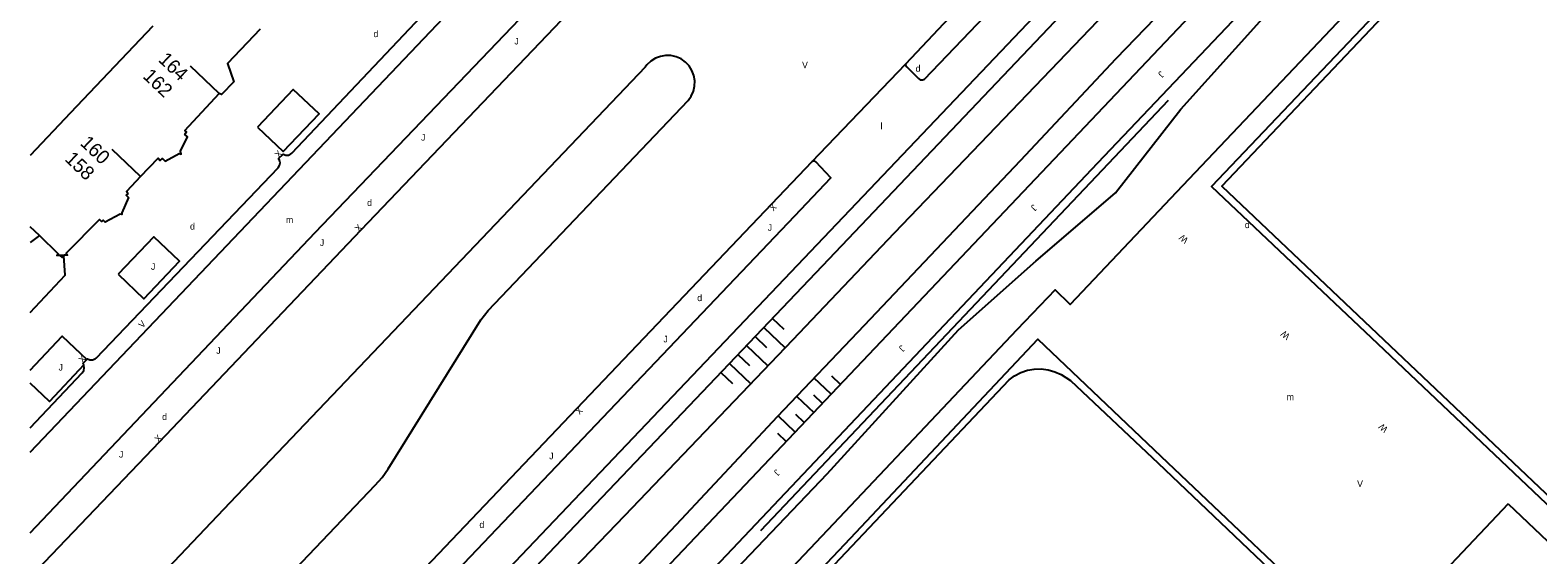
# Model space of a CAD drawing. Extents: x 134999 to 136502, y 457398 to 459002.
# Drawn here: x 135000 to 135114.8, y 457722.8 to 457762.7 of the extents above; entities that cross this region are included whole.
import ezdxf

# ---------------------------------------------------------------- set-up
doc = ezdxf.new("R2010")
doc.units = 0
for name, color, linetype in [('RI_DGTB_15', 7, 'Continuous'), ('RI_DGTB_18', 7, 'Continuous'), ('RI_DGTB_19', 7, 'Continuous'), ('RI_DGTB_2', 7, 'Continuous'), ('RI_DGTB_29', 7, 'Continuous'), ('RI_DGTB_30', 7, 'Continuous'), ('RI_DGTB_31', 7, 'Continuous'), ('RI_DGTB_36', 7, 'Continuous'), ('RI_DGTB_4', 7, 'Continuous'), ('RI_DGTB_43', 7, 'Continuous'), ('RI_DGTB_45', 7, 'Continuous'), ('RI_DGTB_49', 7, 'Continuous'), ('RI_DGTB_5', 7, 'Continuous'), ('RI_DGTB_53', 7, 'Continuous'), ('RI_DGTB_54', 7, 'Continuous'), ('RI_DGTB_55', 7, 'Continuous'), ('RI_DGTB_58', 7, 'Continuous')]:
    doc.layers.add(name, color=color, linetype=linetype)

msp = doc.modelspace()

# ---------------------------------------------------------------- linework, layer by layer
at = {"layer": 'RI_DGTB_15'}
for p, q in [((135014.386, 457757.901), (135012.215, 457759.972)), ((135008.403, 457751.575), (135006.232, 457753.646)), ((135000.718, 457747.078), (135000, 457747.755))]:
    msp.add_line(p, q, dxfattribs=at)
at = {"layer": 'RI_DGTB_18'}
for p, q in [((135044.349, 457717.485), (135122.645, 457800)), ((135056.5, 457740.769), (135057.368, 457739.949)), ((135055.193, 457739.397), (135056.063, 457738.571)), ((135055.847, 457740.083), (135057.474, 457738.542)), ((135054.538, 457738.71), (135056.163, 457737.172)), ((135053.231, 457737.337), (135054.852, 457735.801)), ((135053.885, 457738.023), (135054.759, 457737.195)), ((135052.576, 457736.65), (135053.455, 457735.818)), ((135060.948, 457735.033), (135059.68, 457736.235)), ((135061.687, 457735.757), (135061.034, 457736.375)), ((135058.355, 457734.843), (135059.664, 457733.602)), ((135060.31, 457734.306), (135059.659, 457734.923)), ((135058.245, 457732.13), (135056.945, 457733.362)), ((135058.933, 457732.855), (135058.284, 457733.47)), ((135057.557, 457731.405), (135056.909, 457732.018))]:
    msp.add_line(p, q, dxfattribs=at)
at = {"layer": 'RI_DGTB_19'}
msp.add_line((135076.556, 457745.125), (135082.632, 457750.328), dxfattribs=at)
for points in [[(135046.288, 457715.64), (135081.29, 457752.622), (135113.523, 457786.568), (135126.327, 457800)], [(135082.632, 457750.328), (135087.595, 457756.704), (135097.772, 457768.023), (135114.599, 457785.491), (135126.557, 457798.517), (135128.141, 457800)], [(135076.556, 457745.125), (135070.648, 457739.882), (135060.655, 457728.93)]]:
    msp.add_lwpolyline(points, dxfattribs=at)
at = {"layer": 'RI_DGTB_2'}
for points in [[(135112.51, 457726.659), (135104.213, 457717.881), (135104.437, 457717.669)], [(135112.51, 457726.659), (135121.97, 457717.682)]]:
    msp.add_lwpolyline(points, dxfattribs=at)
at = {"layer": 'RI_DGTB_31'}
for points in [[(135017.307, 457755.344), (135019.264, 457753.484), (135021.989, 457756.35), (135020.032, 457758.21), (135017.307, 457755.344)], [(135006.699, 457744.136), (135008.66, 457742.28), (135011.37, 457745.143), (135009.409, 457746.999), (135006.699, 457744.136)], [(135000, 457736.834), (135002.428, 457739.428), (135004.319, 457737.658)], [(135004.074, 457737.236), (135001.478, 457734.462), (135000, 457735.845)]]:
    msp.add_lwpolyline(points, dxfattribs=at)
at = {"layer": 'RI_DGTB_4'}
for p, q in [((135000.718, 457747.078), (135000, 457746.55)), ((135002.599, 457745.584), (135002.259, 457745.573)), ((135002.599, 457745.584), (135002.561, 457745.545))]:
    msp.add_line(p, q, dxfattribs=at)
for points in [[(135017.516, 457762.79), (135015.022, 457760.174), (135015.504, 457758.79), (135014.577, 457757.831), (135014.386, 457757.901)], [(135008.403, 457751.575), (135009.756, 457752.985), (135009.908, 457752.801), (135010.08, 457752.947), (135010.271, 457752.743), (135011.35, 457753.334), (135011.503, 457753.29), (135011.446, 457753.499), (135011.973, 457754.604), (135011.763, 457754.789), (135011.89, 457754.973), (135011.763, 457755.093), (135014.386, 457757.901)], [(135008.403, 457751.575), (135007.323, 457750.451), (135007.438, 457750.273), (135007.304, 457750.158), (135007.482, 457749.987), (135006.968, 457748.825), (135006.987, 457748.685), (135006.841, 457748.723), (135005.716, 457748.107), (135005.564, 457748.266), (135005.437, 457748.164), (135005.278, 457748.316), (135002.744, 457745.732), (135002.839, 457745.592), (135002.599, 457745.584)], [(135002.259, 457745.573), (135002.032, 457745.566), (135002.152, 457745.68), (135000.718, 457747.078)], [(135002.259, 457745.573), (135002.43, 457745.411), (135002.561, 457745.545)]]:
    msp.add_lwpolyline(points, dxfattribs=at)
at = {"layer": 'RI_DGTB_49'}
for p, q in [((135086.633, 457757.371), (135055.606, 457724.608)), ((135102.561, 457738.856), (135118.445, 457723.788))]:
    msp.add_line(p, q, dxfattribs=at)
for points in [[(135136.578, 457800), (135135.994, 457799.386), (135104.788, 457766.461), (135089.942, 457750.815), (135102.561, 457738.856)], [(135041.457, 457701.863), (135062.45, 457724.054), (135076.702, 457739.2), (135086.075, 457730.29), (135100.567, 457716.545)], [(135060.655, 457728.93), (135023.957, 457690.464), (135009.143, 457672.759)]]:
    msp.add_lwpolyline(points, dxfattribs=at)
at = {"layer": 'RI_DGTB_5'}
for q in [(135009.358, 457763.04), (135000, 457753.172)]:
    msp.add_line((135003.078, 457756.418), q, dxfattribs=at)
at = {"layer": 'RI_DGTB_53'}
msp.add_line((135059.51, 457752.698), (135066.651, 457760.16), dxfattribs=at)
for points in [[(135110.888, 457800), (135012.884, 457697.009), (135002.332, 457685.942), (135000, 457683.414)], [(135112.818, 457800), (135095.163, 457781.447), (135060.288, 457744.746), (135004.929, 457686.625), (135001.305, 457682.789), (135000, 457681.343)], [(135066.651, 457760.16), (135066.639, 457760.054), (135066.741, 457759.929), (135067.616, 457759.038), (135067.761, 457758.95), (135067.931, 457758.936), (135068.088, 457759.001), (135080.746, 457772.249), (135102.232, 457794.938), (135107.068, 457800)], [(135066.651, 457760.16), (135071.226, 457765.037), (135102.532, 457797.93), (135104.511, 457800)], [(135000, 457730.583), (135036.454, 457768.928)], [(135000, 457721.089), (135009.332, 457730.836), (135025.199, 457747.511), (135040.447, 457763.479), (135043.234, 457766.448)], [(135000, 457724.463), (135021.703, 457747.315), (135039.552, 457765.995)], [(135018.918, 457752.951), (135019.266, 457753.288), (135019.458, 457753.213), (135019.663, 457753.215), (135019.852, 457753.296), (135019.928, 457753.358), (135031.576, 457765.695)], [(135000, 457700.507), (135026.253, 457728.08), (135026.785, 457728.674), (135027.255, 457729.318), (135034.317, 457740.673), (135034.858, 457741.372), (135050.093, 457757.363), (135050.328, 457757.695), (135050.494, 457758.067), (135050.585, 457758.464), (135050.596, 457758.871), (135050.528, 457759.272), (135050.382, 457759.653), (135050.165, 457759.997), (135049.886, 457760.293), (135049.553, 457760.529), (135049.182, 457760.695), (135048.785, 457760.785), (135048.378, 457760.796), (135047.976, 457760.728), (135047.596, 457760.583), (135047.251, 457760.366), (135046.955, 457760.086), (135046.814, 457759.904), (135015.211, 457726.732), (135000, 457710.721)], [(135000, 457687.607), (135000.094, 457687.709), (135011.34, 457699.366), (135058.21, 457748.577), (135060.961, 457751.482), (135059.799, 457752.698), (135059.744, 457752.739), (135059.62, 457752.757), (135059.51, 457752.698)], [(135059.51, 457752.698), (135041.586, 457733.895), (135025.591, 457717.073), (135024.258, 457715.744), (135011.135, 457701.876), (135000, 457690.185)], [(135004.319, 457737.658), (135004.354, 457737.691), (135004.546, 457737.616), (135004.751, 457737.618), (135004.94, 457737.699), (135005.016, 457737.761), (135018.882, 457752.24), (135018.994, 457752.415), (135019.032, 457752.619), (135018.992, 457752.823), (135018.918, 457752.951)], [(135000, 457732.446), (135003.97, 457736.643), (135004.082, 457736.818), (135004.12, 457737.022), (135004.08, 457737.226), (135004.074, 457737.236)], [(135004.006, 457737.354), (135004.319, 457737.658)], [(135004.074, 457737.236), (135004.006, 457737.354)]]:
    msp.add_lwpolyline(points, dxfattribs=at)
at = {"layer": 'RI_DGTB_54'}
msp.add_lwpolyline([(135000, 457741.235), (135002.655, 457744.08), (135002.561, 457745.545)], dxfattribs=at)
at = {"layer": 'RI_DGTB_55'}
msp.add_line((135030.109, 457689.141), (135074.519, 457736.101), dxfattribs=at)
for points in [[(135134.278, 457800), (135122.478, 457787.55), (135087.263, 457750.398), (135079.184, 457741.841), (135078.025, 457742.965), (135075.101, 457739.901), (135060.705, 457724.656), (135024.297, 457686.18), (135025.409, 457685.046), (135024.682, 457684.272), (135011.694, 457670.551), (135000, 457658.201)], [(135137.33, 457800), (135090.722, 457750.839), (135118.811, 457724.19)], [(135074.519, 457736.101), (135074.946, 457736.413), (135075.415, 457736.657), (135075.916, 457736.827), (135076.436, 457736.92), (135076.964, 457736.933), (135077.489, 457736.867), (135077.997, 457736.722), (135078.478, 457736.502), (135079.204, 457736.041)], [(135079.204, 457736.041), (135085.861, 457729.75), (135100.647, 457715.705), (135151.738, 457667.306)]]:
    msp.add_lwpolyline(points, dxfattribs=at)
at = {"layer": 'RI_DGTB_58'}
for points in [[(135116.119, 457800), (135114.743, 457798.588), (135107.303, 457790.833), (135099.209, 457782.292), (135081.826, 457764.02), (135065.783, 457747.261), (135058.026, 457739.119), (135045.243, 457725.751), (135038.826, 457719.07), (135033.425, 457713.329), (135028.177, 457707.842), (135024.365, 457703.822), (135019.772, 457699.027), (135015.318, 457694.283), (135012.376, 457691.228), (135006.385, 457684.884), (135002.98, 457681.315), (135001.328, 457679.34), (135000, 457677.847)], [(135120.413, 457800), (135111.967, 457791.303), (135104.476, 457783.422), (135097.525, 457776.163), (135088.592, 457766.7), (135082.652, 457760.54), (135075.358, 457752.786), (135063.49, 457740.237), (135056.863, 457733.276), (135049.182, 457725.071), (135043.123, 457718.651)]]:
    msp.add_lwpolyline(points, dxfattribs=at)

# ---------------------------------------------------------------- texts
at = {"layer": 'RI_DGTB_29'}
for p in [(135026.136, 457762.192), (135067.408, 457759.557), (135025.651, 457749.336), (135012.168, 457747.539), (135092.468, 457747.652), (135050.781, 457742.094), (135010.046, 457733.04), (135034.2, 457724.828)]:
    msp.add_text('d', height=0.5, dxfattribs=at).set_placement(p)
at = {"layer": 'RI_DGTB_30'}
for p in [(135058.762, 457759.828), (135101.017, 457727.949)]:
    msp.add_text('V', height=0.5, dxfattribs=at).set_placement(p)
for s, height, rotation, p in [('X', 0.499, 46.46737, (135018.932, 457752.966)), ('X', 0.5, 226.51948, (135056.523, 457749.562)), ('X', 0.5, 46.42227, (135025.027, 457747.33)), ('W', 0.5, 139.91229, (135088.212, 457746.811)), ('V', 0.499, 46.46737, (135008.548, 457739.999)), ('W', 0.5, 141.89972, (135095.953, 457739.505)), ('X', 0.499, 46.46737, (135003.996, 457737.344)), ('X', 0.5, 226.36538, (135041.759, 457734.076)), ('W', 0.5, 138.02278, (135103.407, 457732.401)), ('X', 0.5, 46.42227, (135009.777, 457731.304))]:
    msp.add_text(s, height=height, rotation=rotation, dxfattribs=at).set_placement(p)
at = {"layer": 'RI_DGTB_31'}
for p in [(135036.863, 457761.632), (135029.753, 457754.312), (135056.143, 457747.441), (135022.049, 457746.295), (135009.196, 457744.478), (135048.207, 457738.952), (135014.166, 457738.074), (135002.162, 457736.809), (135006.76, 457730.178), (135039.511, 457730.049)]:
    msp.add_text('J', height=0.5, dxfattribs=at).set_placement(p)
for p in [(135086.038, 457759.645), (135076.356, 457749.499), (135066.305, 457738.781), (135056.794, 457729.335)]:
    msp.add_text('J', height=0.499, rotation=226.85182, dxfattribs=at).set_placement(p)
at = {"layer": 'RI_DGTB_36'}
for s, rotation, p in [('164', 316.3587, (135009.697, 457760.396)), ('162', 316.367, (135008.514, 457759.145)), ('160', 316.3587, (135003.747, 457754.042)), ('158', 316.367, (135002.575, 457752.837))]:
    msp.add_text(s, height=1.054, rotation=rotation, dxfattribs=at).set_placement(p)
at = {"layer": 'RI_DGTB_43'}
for s, p in [('l', (135064.734, 457755.177)), ('m', (135019.478, 457748.032))]:
    msp.add_text(s, height=0.5, dxfattribs=at).set_placement(p)
at = {"layer": 'RI_DGTB_45'}
msp.add_text('m', height=0.5, dxfattribs=at).set_placement((135095.653, 457734.551))

doc.saveas('drawing.dxf')
